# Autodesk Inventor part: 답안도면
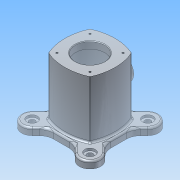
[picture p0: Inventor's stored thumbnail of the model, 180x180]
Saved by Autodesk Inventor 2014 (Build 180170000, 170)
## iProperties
Created: 2016-05
Part Number: 답안도면
Material: 알루미늄 6061
Document SubType Name: Modeling
Designer: net
Density: 2.71 g/cm^3
Appearance: 알루미늄 - 평지
Author: net
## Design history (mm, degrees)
sketch "스케치1"
  geometry: L1 (-43, -43)-(43, 43); L2 (0, 0)-(50, 0); L3 (-2.165, -2.165)-(47.835, -2.165); L4 (-1.189, 0)-(48.811, 0); L5 (0, 0)-(50, 0); A1 r 85.579 centre (42.579, 0) between (-35.355, 35.355) and (-35.355, -35.355); A2 r 85.579 centre (0, -42.579) between (35.355, 35.355) and (-35.355, 35.355); A3 r 85.579 centre (-42.579, 0) between (35.355, -35.355) and (35.355, 35.355); A4 r 85.579 centre (0, 42.579) between (-35.355, -35.355) and (35.355, -35.355)
  constraints: 10 end point, 8 point on circle, 4 centre point, 4 horizontal, 1 midpoint, 1 point on line
  dimensions: "d5" = 50 distance of L2.start A2.start; "d13" = 50 distance of L2.start A3.start; "d14" = 50 distance of L2.start A1.start
extrude "돌출1" new body sketch "스케치1" stored distance "d15" = 98; taper "d16" = 0 deg
sketch "스케치3"
  geometry: L1 (-23.544, -49)-(23.544, -49); L2 (49, -23.544)-(49, 23.544); L3 (-23.544, 49)-(-36.701, 62.157); L4 (-49, 23.544)-(-62.157, 36.701); L5 (-49, -23.544)-(-62.157, -36.701); L6 (-23.544, -49)-(-36.701, -62.157); L7 (23.544, -49)-(36.701, -62.157); L8 (49, -23.544)-(62.157, -36.701); L9 (49, 23.544)-(62.157, 36.701); L10 (23.544, 49)-(36.701, 62.157); L11 (-49, 23.544)-(-49, -23.544); L12 (23.544, 49)-(-23.544, 49); L13 (61.728, -36.272)-(49, -23.544); L14 (36.272, -61.728)-(23.544, -49); A1 r 18 centre (-49.429, 49.429) between (-36.701, 62.157) and (-62.157, 36.701); A2 r 18 centre (-49.429, -49.429) between (-62.157, -36.701) and (-36.701, -62.157); A3 r 18 centre (49.429, -49.429) between (36.701, -62.157) and (62.157, -36.701); A4 r 18 centre (49.429, 49.429) between (62.157, 36.701) and (36.701, 62.157); 2 further points
  constraints: 28 end point, 8 point on circle, 4 centre point, 2 parallel, 1 horizontal, 1 perpendicular, 33 other
  dimensions: "d33" = 360 deg dimension on point (0, 0) L3.start (derived)
extrude "돌출3" join sketch "스케치3" distance "d34" = 12; taper "d35" = 0 deg
sketch "스케치4"
  geometry: C1 r 25 at (0, 0); 1 further point
  constraints: 1 centre point, 1 coincident
  dimensions: "d36" = 50 diameter of C1
extrude "돌출4" cut sketch "스케치4" distance "d37" = 12; taper "d38" = 0 deg
sketch "스케치5"
  geometry: C1 r 25 at (0, 0); 1 further point
  constraints: 1 centre point, 1 coincident
  dimensions: "d39" = 50 diameter of C1
extrude "돌출5" cut sketch "스케치5" distance "d40" = 12; taper "d41" = 0 deg
sketch "스케치6"
  geometry: C1 r 35 at (0, 0); 1 further point
  constraints: 1 centre point, 1 coincident
  dimensions: "d42" = 70 diameter of C1
extrude "돌출6" cut sketch "스케치6" distance "d43" = 37; taper "d45" = 0 deg; dims "d44" = 49, "d46" = 0
node "작업 평면1"
sketch "스케치7"
  geometry: L1 (35.355, 49)-(-35.355, 49) reference; C1 r 20 at (0, 0); 1 further point
  constraints: 1 centre point, 1 coincident
  dimensions: "d48" = 40 diameter of C1
extrude "돌출7" join sketch "스케치7" stored distance "d49" = 37; taper "d50" = 0 deg
sketch "스케치8"
  geometry: C1 r 20 at (0, 0) reference; C2 r 15 at (0, 0)
  constraints: 1 centre point, 1 coincident
  dimensions: "d51" = 30 diameter of C2
extrude "돌출8" cut sketch "스케치8" distance "d52" = 8; taper "d53" = 0 deg
sketch "스케치9"
  geometry: C1 r 15 at (0, 0) reference; C2 r 12.5 at (0, 0)
  constraints: 1 centre point, 1 coincident
  dimensions: "d54" = 25 diameter of C2
extrude "돌출9" cut sketch "스케치9" distance "d55" = 30; taper "d56" = 0 deg
feature "면 기울기1" dims angle "d57" = 10 deg
sketch "스케치11"
  geometry: L1 (0, 0)-(40, 0); C1 r 25 at (0, 0) reference; 4 further points
  constraints: 2 end point, 1 horizontal, 5 other
  dimensions: "d70" = 360 deg dimension on L1.start point (-28.284, 28.284) (derived)
hole "구멍2" sketch "스케치11" at (-28.284, 28.284), (28.284, 28.284), (28.284, -28.284), (-28.284, -28.284) diameter "d72" = 3.242; stored, may be unused: countersink angle "d76" = 90 deg, drill point angle "d78" = 118 deg; dims "d73" = 7, "d74" = 18, "d75" = 4, "d77" = 10
sketch "스케치12"
  geometry: L1 (0, 0)-(40, 0); C1 r 25 at (0, 0) reference; 5 further points
  constraints: 2 coincident, 2 end point, 1 horizontal, 5 other
  dimensions: "d84" = 360 deg dimension on C1.centre point (-28.284, 28.284) (derived)
hole "구멍3" sketch "스케치12" at (28.284, 28.284), (28.284, -28.284), (-28.284, -28.284), (-28.284, 28.284) diameter "d86" = 3.242; stored, may be unused: countersink angle "d90" = 90 deg, drill point angle "d92" = 118 deg; dims "d87" = 7, "d88" = 18, "d89" = 4, "d91" = 10
node "작업 평면2"
sketch "스케치13"
  geometry: L1 (0, 0)-(29, 0); L2 (35.355, 49)-(-35.355, 49) reference; L3 (-25.998, 20.739)-(-25.998, -20.739); L4 (-25.998, -20.739)-(-32.002, -20.739); L5 (-32.002, -20.739)-(-32.002, 20.739); L6 (-32.002, 20.739)-(-25.998, 20.739); 1 further point
  constraints: 2 end point, 1 horizontal, 3 other
  dimensions: "d96" = 41.47897 distance of L3.start L3.end; "d97" = 6.00407 distance of L3.end L4.end; "d98" = 20.73948 vertical distance of L4.end point (-29, 0) (= 0.5 x d96); "d99" = 3.00204 horizontal distance of point (-29, 0) L4.end (= 0.5 x d97)
feature "엠보싱1" sketch "스케치13" dims "d33" = 360 deg (derived), "d100" = 0.5, "d101" = 0
fillet "모깎기1" dims "d102" = 3
fillet "모깎기2" dims "d103" = 3
chamfer "모따기1" distance "d104" = 1; stored, may be unused: second distance "d105" = 2, angle "d106" = 45 deg
fillet "모깎기3" dims "d107" = 3
node "작업 평면3"
sketch "스케치17"
  geometry: L1 (0, 46)-(24.787, 46) reference; L2 (24.787, 46)-(38.823, 60.036) reference; L3 (60.036, 38.823)-(46, 24.787) reference; L4 (46, 24.787)-(46, 0) reference; L5 (24.787, -46)-(0, -46) reference; L6 (38.823, -60.036)-(24.787, -46) reference; L7 (46, -24.787)-(60.036, -38.823) reference; L8 (46, 0)-(46, -24.787) reference; L9 (-46, 0)-(-46, 24.787) reference; L10 (-46, 24.787)-(-60.036, 38.823) reference; L11 (-38.823, 60.036)-(-24.787, 46) reference; L12 (-24.787, 46)-(0, 46) reference; L13 (0, -46)-(-24.787, -46) reference; L14 (-24.787, -46)-(-38.823, -60.036) reference; L15 (-60.036, -38.823)-(-46, -24.787) reference; L16 (-46, -24.787)-(-46, 0) reference; L17 (0, 0)-(49.497, -49.497); L18 (0, 0)-(70, 0); C1 r 32 at (0, 0) reference; C2 r 25 at (0, 0) reference; A1 r 6 centre (33.083, 33.083) between (38.581, 35.487) and (35.487, 38.581) reference; A2 r 88.579 centre (0, -42.579) between (35.487, 38.581) and (0, 46) reference; A3 r 15 centre (49.429, 49.429) between (60.036, 38.823) and (38.823, 60.036) reference; A4 r 88.579 centre (-42.579, 0) between (38.581, -35.487) and (46, 0) reference; A5 r 6 centre (33.083, -33.083) between (35.487, -38.581) and (38.581, -35.487) reference; A6 r 88.579 centre (0, 42.579) between (0, -46) and (35.487, -38.581) reference; A7 r 15 centre (49.429, -49.429) between (38.823, -60.036) and (60.036, -38.823) reference; A8 r 88.579 centre (-42.579, 0) between (46, 0) and (38.581, 35.487) reference; A9 r 88.579 centre (0, -42.579) between (0, 46) and (-35.487, 38.581) reference; A10 r 6 centre (-33.083, 33.083) between (-35.487, 38.581) and (-38.581, 35.487) reference; A11 r 88.579 centre (42.579, 0) between (-38.581, 35.487) and (-46, 0) reference; A12 r 15 centre (-49.429, 49.429) between (-38.823, 60.036) and (-60.036, 38.823) reference; A13 r 88.579 centre (0, 42.579) between (-35.487, -38.581) and (0, -46) reference; A14 r 15 centre (-49.429, -49.429) between (-60.036, -38.823) and (-38.823, -60.036) reference; A15 r 88.579 centre (42.579, 0) between (-46, 0) and (-38.581, -35.487) reference; A16 r 6 centre (-33.083, -33.083) between (-38.581, -35.487) and (-35.487, -38.581) reference; 6 further points
  constraints: 4 end point, 2 coincident, 1 equal length, 1 horizontal, 1 perpendicular, 5 other
  dimensions: "d132" = 70 distance of L17.start L17.end; "d133" = 45 deg angle of L17 L18 (derived); "d136" = 360 deg dimension on point (0, 0) point (49.497, -49.497) (derived)
hole "구멍5" sketch "스케치17" at (49.497, 49.497), (-49.497, 49.497), (-49.497, -49.497), (49.497, -49.497) diameter "d138" = 10; stored, may be unused: countersink angle "d142" = 90 deg, drill point angle "d144" = 0 deg; dims "d139" = 6, "d140" = 18, "d141" = 4, "d143" = 30
fillet "모깎기4" dims "d145" = 25
node "솔리드1"
node "절단 모서리 투영2"
other parameters: "d24" = 36, "d47" = 55, "d93" = 55, "d131" = -49
